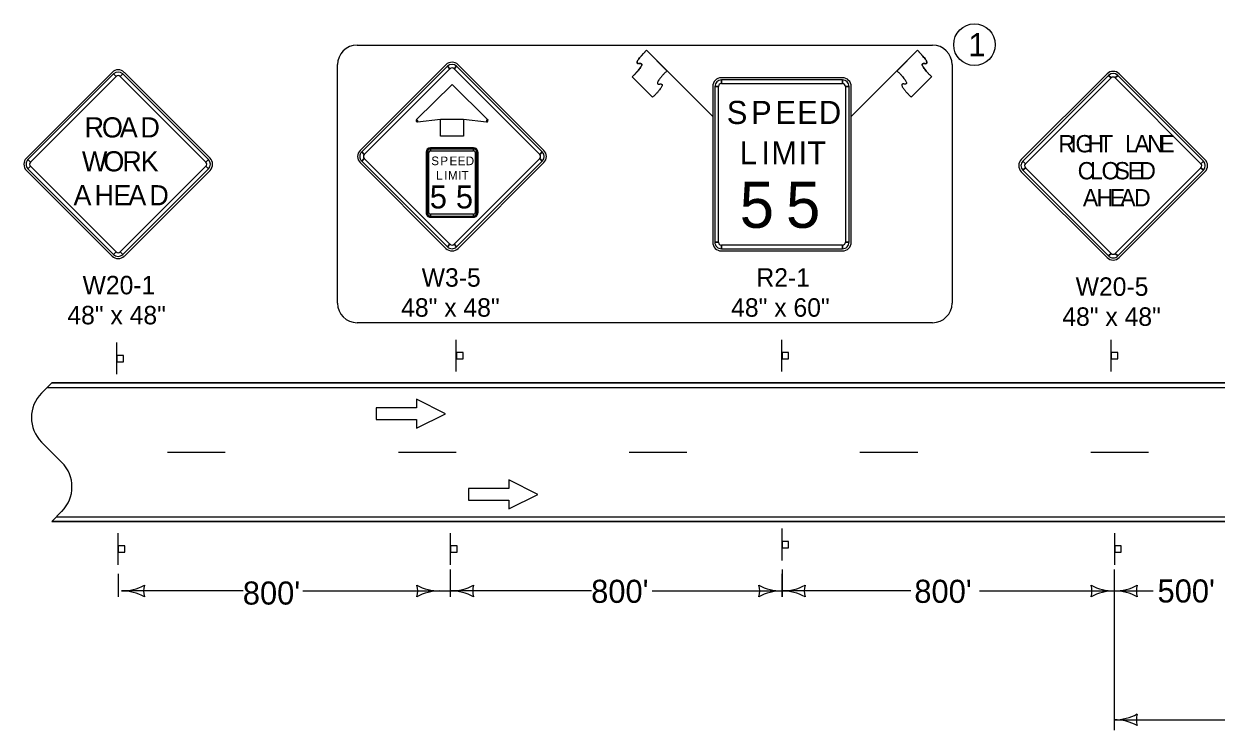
# Model space of a CAD drawing. Extents: x 10133 to 2270741, y 5363 to 1733450.
# Drawn here: x 28142 to 29175, y 11512 to 12124 of the extents above; entities that cross this region are included whole.
import ezdxf

# ---------------------------------------------------------------- set-up
doc = ezdxf.new("R2010")
doc.units = 0
for name, color, linetype in [('dsnNonPlotable', 7, 'Continuous'), ('dsnShtPlotShapeBatchPrint', 7, 'Continuous'), ('dsnStdBorder', 7, 'Continuous'), ('Level 12', 7, 'Continuous'), ('Level 2', 7, 'Continuous')]:
    doc.layers.add(name, color=color, linetype=linetype)

msp = doc.modelspace()

# ---------------------------------------------------------------- linework, layer by layer
at = {"layer": 'dsnNonPlotable'}
for p, q in [((28165.8, 11812.6), (28157, 11803.8)), ((28157, 11761.4), (28174.5, 11743.8)), ((28174.5, 11701.4), (28165.8, 11692.6)), ((28169.7, 11696.6), (29666.9, 11696.6))]:
    msp.add_line(p, q, dxfattribs=at)
for points in [[(28161.8, 11808.6), (30191.3, 11808.6)], [(28266.1, 11752.6), (28316.1, 11752.6)], [(28466.1, 11752.6), (28516.1, 11752.6)], [(28666.1, 11752.6), (28716.1, 11752.6)], [(28866, 11752.6), (28916, 11752.6)], [(29066, 11752.6), (29116, 11752.6)]]:
    msp.add_lwpolyline(points, dxfattribs=at)
for centre, start, end in [((28178.2, 11782.6), 135, 225), ((28153.3, 11722.6), 315, 45)]:
    msp.add_arc(centre, 30, start, end, dxfattribs=at)
at = {"layer": 'dsnShtPlotShapeBatchPrint'}
msp.add_circle((28965.2, 12105.7), 18, dxfattribs=at)
at = {"layer": 'dsnStdBorder'}
for p, q in [((28738.4, 12043.5), (28681.1, 12100.8)), ((28681.1, 12100.8), (28698.8, 12083.1)), ((28858.4, 12043.5), (28915.8, 12100.8)), ((28915.8, 12100.8), (28898.1, 12083.1)), ((28507.2, 12088.3), (28433, 12014.1)), ((28508.6, 12087), (28510.8, 12084.8)), ((28514.3, 12084.8), (28516.5, 12087)), ((28592.1, 12014.1), (28517.9, 12088.3)), ((28218, 12081.7), (28143.8, 12007.4)), ((28219.4, 12080.4), (28221.6, 12078.1)), ((28225.1, 12078.1), (28227.3, 12080.4)), ((28302.9, 12007.4), (28228.7, 12081.7)), ((28668.7, 12077.8), (28686.4, 12060.1)), ((28686.4, 12060.1), (28668.7, 12077.8)), ((28850.9, 12077), (28745.9, 12077)), ((28928.1, 12077.8), (28910.5, 12060.1)), ((28910.5, 12060.1), (28928.1, 12077.8)), ((29080.1, 12080.4), (29005.8, 12006.2)), ((29081.4, 12079.1), (29083.6, 12076.9)), ((29087.1, 12076.9), (29089.3, 12079.1)), ((29164.9, 12006.2), (29090.7, 12080.4)), ((28738.4, 12069.5), (28738.4, 11934.5)), ((28740.3, 12069.5), (28743.4, 12069.5)), ((28745.9, 12072), (28745.9, 12075.2)), ((28850.9, 12075.2), (28850.9, 12072)), ((28853.4, 12069.5), (28856.6, 12069.5)), ((28858.4, 11934.5), (28858.4, 12069.5)), ((28482.6, 12040), (28481.7, 12040.9)), ((28482.7, 12038.8), (28482.6, 12040)), ((28542.6, 12040), (28542.4, 12038.8)), ((28543.4, 12040.9), (28542.6, 12040)), ((28531.3, 12016.3), (28493.8, 12016.3)), ((28493.8, 12013.8), (28493.8, 12015.3)), ((28531.3, 12015.3), (28531.3, 12013.8)), ((28147.3, 12003.9), (28145.1, 12006.1)), ((28301.6, 12006.1), (28299.4, 12003.9)), ((28433, 12003.5), (28507.2, 11929.2)), ((28436.5, 12010.5), (28434.3, 12012.8)), ((28434.3, 12004.8), (28436.5, 12007)), ((28490.1, 12012.5), (28490.1, 11960)), ((28491, 12012.5), (28492.6, 12012.5)), ((28517.9, 11929.2), (28592.1, 12003.5)), ((28532.6, 12012.5), (28534.1, 12012.5)), ((28535.1, 11960), (28535.1, 12012.5)), ((28590.8, 12012.8), (28588.6, 12010.5)), ((28588.6, 12007), (28590.8, 12004.8)), ((29009.3, 12002.6), (29007.1, 12004.9)), ((29163.6, 12004.9), (29161.4, 12002.6)), ((28143.8, 11996.8), (28218, 11922.6)), ((28145.1, 11998.2), (28147.3, 12000.4)), ((28228.7, 11922.6), (28302.9, 11996.8)), ((28299.4, 12000.4), (28301.6, 11998.2)), ((29005.8, 11995.6), (29080.1, 11921.3)), ((29007.1, 11996.9), (29009.3, 11999.1)), ((29090.7, 11921.3), (29164.9, 11995.6)), ((29161.4, 11999.1), (29163.6, 11996.9)), ((28492.6, 11960), (28491, 11960)), ((28493.8, 11957.2), (28493.8, 11958.8)), ((28493.8, 11956.3), (28531.3, 11956.3)), ((28531.3, 11958.8), (28531.3, 11957.2)), ((28534.1, 11960), (28532.6, 11960)), ((28510.8, 11932.8), (28508.6, 11930.6)), ((28516.5, 11930.6), (28514.3, 11932.8)), ((28743.4, 11934.5), (28740.3, 11934.5)), ((28745.9, 11928.9), (28745.9, 11932)), ((28850.9, 11932), (28850.9, 11928.9)), ((28856.6, 11934.5), (28853.4, 11934.5)), ((28221.6, 11926.1), (28219.4, 11923.9)), ((28227.3, 11923.9), (28225.1, 11926.1)), ((28745.9, 11927), (28850.9, 11927)), ((29083.6, 11924.9), (29081.4, 11922.7)), ((29089.3, 11922.7), (29087.1, 11924.9)), ((28516.3, 11822.6), (28516.3, 11850.1)), ((28798.4, 11822.6), (28798.4, 11850.1)), ((29083.6, 11822.6), (29083.6, 11850.1)), ((28222.1, 11820.1), (28222.1, 11847.6)), ((28798.5, 11658.9), (28798.5, 11686.4)), ((28223.3, 11655.1), (28223.3, 11682.6)), ((28511.2, 11655.1), (28511.2, 11682.6)), ((29086.7, 11655.1), (29086.7, 11682.6))]:
    msp.add_line(p, q, dxfattribs=at)
for points in [[(28430.4, 12105.4), (28928.8, 12105.4)], [(28413.3, 11881.8), (28413.3, 12088.4)], [(28945.8, 12088.4), (28945.8, 11881.8)], [(28928.8, 11864.7), (28430.4, 11864.7)], [(28446.8, 11791), (28446.8, 11781), (28481.8, 11781), (28481.8, 11773.5), (28506.8, 11786), (28481.8, 11798.5), (28481.8, 11791), (28446.8, 11791)], [(28526.8, 11721.1), (28526.8, 11711.1), (28561.8, 11711.1), (28561.8, 11703.6), (28586.8, 11716.1), (28561.8, 11728.6), (28561.8, 11721.1), (28526.8, 11721.1)]]:
    msp.add_lwpolyline(points, dxfattribs=at)
for points in [[(28508.6, 12087), (28434.3, 12012.8), (28436.5, 12010.5), (28510.8, 12084.8), (28508.6, 12087)], [(28590.8, 12012.8), (28516.5, 12087), (28514.3, 12084.8), (28588.6, 12010.5), (28590.8, 12012.8)], [(28219.4, 12080.4), (28145.1, 12006.1), (28147.3, 12003.9), (28221.6, 12078.1), (28219.4, 12080.4)], [(28301.6, 12006.1), (28227.3, 12080.4), (28225.1, 12078.1), (28299.4, 12003.9), (28301.6, 12006.1)], [(29081.4, 12079.1), (29007.1, 12004.9), (29009.3, 12002.6), (29083.6, 12076.9), (29081.4, 12079.1)], [(29163.6, 12004.9), (29089.3, 12079.1), (29087.1, 12076.9), (29161.4, 12002.6), (29163.6, 12004.9)], [(28512.6, 12071.3), (28481.7, 12040.9), (28482.6, 12040), (28482.7, 12038.8), (28502.6, 12041.3), (28522.6, 12041.3), (28542.4, 12038.8), (28542.6, 12040), (28543.4, 12040.9), (28512.6, 12071.3)], [(28740.3, 12069.5), (28740.3, 11934.5), (28743.4, 11934.5), (28743.4, 12069.5), (28740.3, 12069.5)], [(28850.9, 12075.2), (28745.9, 12075.2), (28745.9, 12072), (28850.9, 12072), (28850.9, 12075.2)], [(28856.6, 11934.5), (28856.6, 12069.5), (28853.4, 12069.5), (28853.4, 11934.5), (28856.6, 11934.5)], [(28522.6, 12026.3), (28502.6, 12026.3), (28502.6, 12041.3), (28522.6, 12041.3), (28522.6, 12026.3)], [(28531.3, 12015.3), (28493.8, 12015.3), (28493.8, 12013.8), (28531.3, 12013.8), (28531.3, 12015.3)], [(28434.3, 12004.8), (28508.6, 11930.6), (28510.8, 11932.8), (28436.5, 12007), (28434.3, 12004.8)], [(28491, 12012.5), (28491, 11960), (28492.6, 11960), (28492.6, 12012.5), (28491, 12012.5)], [(28516.5, 11930.6), (28590.8, 12004.8), (28588.6, 12007), (28514.3, 11932.8), (28516.5, 11930.6)], [(28534.1, 11960), (28534.1, 12012.5), (28532.6, 12012.5), (28532.6, 11960), (28534.1, 11960)], [(28145.1, 11998.2), (28219.4, 11923.9), (28221.6, 11926.1), (28147.3, 12000.4), (28145.1, 11998.2)], [(28227.3, 11923.9), (28301.6, 11998.2), (28299.4, 12000.4), (28225.1, 11926.1), (28227.3, 11923.9)], [(29007.1, 11996.9), (29081.4, 11922.7), (29083.6, 11924.9), (29009.3, 11999.1), (29007.1, 11996.9)], [(29089.3, 11922.7), (29163.6, 11996.9), (29161.4, 11999.1), (29087.1, 11924.9), (29089.3, 11922.7)], [(28493.8, 11957.2), (28531.3, 11957.2), (28531.3, 11958.8), (28493.8, 11958.8), (28493.8, 11957.2)], [(28745.9, 11928.9), (28850.9, 11928.9), (28850.9, 11932), (28745.9, 11932), (28745.9, 11928.9)], [(28516.4, 11839.1), (28516.4, 11833.4), (28522.1, 11833.4), (28522.1, 11839.1)], [(28798.5, 11839.1), (28798.5, 11833.4), (28804.2, 11833.4), (28804.2, 11839.1)], [(29083.7, 11839.1), (29083.7, 11833.4), (29089.3, 11833.4), (29089.3, 11839.1)], [(28222.2, 11836.5), (28222.2, 11830.9), (28227.8, 11830.9), (28227.8, 11836.5)], [(28798.5, 11675.3), (28798.5, 11669.7), (28804.2, 11669.7), (28804.2, 11675.3)], [(28223.4, 11671.6), (28223.4, 11665.9), (28229, 11665.9), (28229, 11671.6)], [(28511.3, 11671.6), (28511.3, 11665.9), (28517, 11665.9), (28517, 11671.6)], [(29086.8, 11671.6), (29086.8, 11665.9), (29092.4, 11665.9), (29092.4, 11671.6)]]:
    msp.add_lwpolyline(points, close=True, dxfattribs=at)
for centre, radius, start, end in [((28430.4, 12088.4), 17, 90, 180), ((28928.8, 12088.4), 17, 0, 90), ((28512.6, 12083), 7.5, 45, 134.9997), ((28512.6, 12083), 5.62, 45, 134.9997), ((28223.3, 12076.4), 7.5, 45, 134.9997), ((28223.3, 12076.4), 5.62, 45, 134.9997), ((28223.3, 12076.4), 2.5, 45, 134.9997), ((28512.6, 12083), 2.5, 45, 134.9997), ((28745.9, 12069.5), 7.5, 90.0002, 179.9998), ((28850.9, 12069.5), 7.5, 0, 90.0002), ((29085.4, 12075.1), 7.5, 45, 134.9997), ((29085.4, 12075.1), 5.62, 45, 134.9997), ((29085.4, 12075.1), 2.5, 45, 134.9997), ((28745.9, 12069.5), 5.62, 90.0002, 179.9998), ((28745.9, 12069.5), 2.5, 90.0002, 179.9998), ((28850.9, 12069.5), 5.62, 0, 90.0002), ((28850.9, 12069.5), 2.5, 0, 90.0002), ((28482.6, 12040), 1.25, 134.9997, 277.1529), ((28542.6, 12040), 1.25, 262.8473, 44.9998), ((28438.3, 12008.8), 7.5, 134.9997, 225), ((28493.8, 12012.5), 3.75, 90.0002, 179.9998), ((28493.8, 12012.5), 2.81, 90.0002, 179.9998), ((28493.8, 12012.5), 1.25, 90.0002, 179.9998), ((28531.3, 12012.5), 3.75, 0, 90.0002), ((28531.3, 12012.5), 2.81, 0, 90.0002), ((28531.3, 12012.5), 1.25, 0, 90.0002), ((28586.8, 12008.8), 7.5, 315.0002, 44.9998), ((28149.1, 12002.1), 7.5, 134.9997, 225), ((28149.1, 12002.1), 5.62, 134.9997, 225), ((28149.1, 12002.1), 2.5, 134.9997, 225), ((28297.6, 12002.1), 2.5, 315.0002, 44.9998), ((28297.6, 12002.1), 5.62, 315.0002, 44.9998), ((28297.6, 12002.1), 7.5, 315.0002, 44.9998), ((28438.3, 12008.8), 5.62, 134.9997, 225), ((28438.3, 12008.8), 2.5, 134.9997, 225), ((28586.8, 12008.8), 2.5, 315.0002, 44.9998), ((28586.8, 12008.8), 5.62, 315.0002, 44.9998), ((29011.1, 12000.9), 7.5, 134.9997, 225), ((29011.1, 12000.9), 5.62, 134.9997, 225), ((29159.6, 12000.9), 5.62, 315.0002, 44.9998), ((29159.6, 12000.9), 7.5, 315.0002, 44.9998), ((29011.1, 12000.9), 2.5, 134.9997, 225), ((29159.6, 12000.9), 2.5, 315.0002, 44.9998), ((28493.8, 11960), 3.75, 179.9998, 270.0001), ((28493.8, 11960), 2.81, 179.9998, 270.0001), ((28493.8, 11960), 1.25, 179.9998, 270.0001), ((28531.3, 11960), 3.75, 270.0001, 0.0003), ((28531.3, 11960), 2.81, 270.0001, 0.0003), ((28531.3, 11960), 1.25, 270.0001, 0.0003), ((28512.6, 11934.5), 2.5, 225, 315.0002), ((28745.9, 11934.5), 7.5, 179.9998, 270.0001), ((28745.9, 11934.5), 5.62, 179.9998, 270.0001), ((28745.9, 11934.5), 2.5, 179.9998, 270.0001), ((28850.9, 11934.5), 7.5, 270.0001, 0.0003), ((28850.9, 11934.5), 5.62, 270.0001, 0.0003), ((28850.9, 11934.5), 2.5, 270.0001, 0.0003), ((28223.3, 11927.9), 7.5, 225, 315.0002), ((28223.3, 11927.9), 5.62, 225, 315.0002), ((28223.3, 11927.9), 2.5, 225, 315.0002), ((28512.6, 11934.5), 7.5, 225, 315.0002), ((28512.6, 11934.5), 5.62, 225, 315.0002), ((29085.4, 11926.6), 7.5, 225, 315.0002), ((29085.4, 11926.6), 5.62, 225, 315.0002), ((29085.4, 11926.6), 2.5, 225, 315.0002), ((28430.4, 11881.8), 17, 180, 270), ((28928.8, 11881.8), 17, 270, 0)]:
    msp.add_arc(centre, radius, start, end, dxfattribs=at)
for points in [[(28681.1, 12100.8), (28668.7, 12088.4), (28681.1, 12090.2), (28668.7, 12077.8)], [(28668.7, 12077.8), (28681.1, 12090.2), (28668.7, 12088.4), (28681.1, 12100.8)], [(28915.8, 12100.8), (28928.1, 12088.4), (28915.8, 12090.2), (28928.1, 12077.8)], [(28928.1, 12077.8), (28915.8, 12090.2), (28928.1, 12088.4), (28915.8, 12100.8)], [(28698.8, 12083.1), (28686.4, 12070.7), (28698.8, 12072.5), (28686.4, 12060.1)], [(28698.8, 12083.1), (28686.4, 12070.7), (28698.8, 12072.5), (28686.4, 12060.1)], [(28898.1, 12083.1), (28910.4, 12070.7), (28898.1, 12072.5), (28910.5, 12060.1)], [(28898.1, 12083.1), (28910.4, 12070.7), (28898.1, 12072.5), (28910.5, 12060.1)]]:
    msp.add_open_spline(points, degree=2, dxfattribs=at)
at = {"layer": 'Level 12'}
for p, q in [((28223.3, 11647.1), (28223.3, 11627.4)), ((28510.9, 11650.9), (28510.9, 11627.4)), ((28798.4, 11647.1), (28798.4, 11627.4)), ((28798.5, 11650.9), (28798.5, 11627.4)), ((29086.1, 11650.9), (29086.1, 11511.8)), ((28331.5, 11632.4), (28226.1, 11632.4)), ((28383.4, 11632.4), (28510.9, 11632.4)), ((28633.3, 11632.4), (28510.9, 11632.4)), ((28686, 11632.4), (28798.5, 11632.4)), ((28910.2, 11632.4), (28798.5, 11632.4)), ((28969.6, 11632.4), (29086.1, 11632.4)), ((29086.9, 11632.4), (29119.9, 11632.4)), ((29086.1, 11520.8), (29195.4, 11520.8))]:
    msp.add_line(p, q, dxfattribs=at)
for centre, radius, start, end in [((28226.1, 11674.9), 42.5, 270, 298.0725), ((28226.1, 11589.9), 42.5, 61.9275, 90), ((28261.7, 11632.4), 16.4, 162.2666, 197.7334), ((28466.5, 11632.4), 16.4, 342.2667, 17.7334), ((28502.1, 11674.9), 42.5, 241.9275, 270), ((28502.1, 11589.9), 42.5, 90, 118.0725), ((28511.2, 11674.9), 42.5, 270, 298.0725), ((28511.2, 11589.9), 42.5, 61.9275, 90), ((28546.9, 11632.4), 16.4, 162.2666, 197.7334), ((28762.8, 11632.4), 16.4, 342.2667, 17.7334), ((28798.4, 11674.9), 42.5, 241.9275, 270), ((28798.4, 11589.9), 42.5, 90, 118.0725), ((28798.4, 11674.9), 42.5, 270, 298.0725), ((28798.4, 11589.9), 42.5, 61.9275, 90), ((28834.1, 11632.4), 16.4, 162.2666, 197.7334), ((29050.6, 11632.4), 16.4, 342.2667, 17.7334), ((29086.3, 11674.9), 42.5, 241.9275, 270), ((29086.3, 11589.9), 42.5, 90, 118.0725), ((29086.3, 11674.9), 42.5, 270, 298.0725), ((29086.3, 11589.9), 42.5, 61.9275, 90), ((29121.9, 11632.4), 16.4, 162.2666, 197.7334), ((29086.3, 11563.3), 42.5, 270, 298.0725), ((29086.3, 11478.3), 42.5, 61.9275, 90), ((29121.9, 11520.8), 16.4, 162.2666, 197.7334)]:
    msp.add_arc(centre, radius, start, end, dxfattribs=at)
at = {"layer": 'Level 2'}
for p, q in [((28157, 11803.8), (28161.8, 11808.6)), ((28165.8, 11812.6), (28161.8, 11808.6)), ((28161.8, 11808.6), (29379, 11808.6)), ((28161.8, 11808.6), (29957.3, 11808.6)), ((28165.8, 11812.6), (30292.4, 11812.6)), ((29955.6, 11812.6), (28165.8, 11812.6)), ((28174.5, 11743.8), (28157, 11761.4)), ((28165.8, 11692.6), (28174.5, 11701.4)), ((28165.8, 11692.6), (30498, 11692.6)), ((29210.2, 11692.6), (28165.8, 11692.6))]:
    msp.add_line(p, q, dxfattribs=at)
msp.add_lwpolyline([(28161.8, 11808.6), (28161.8, 11808.6)], dxfattribs=at)
msp.add_lwpolyline([(28161.8, 11808.6), (28161.8, 11808.6)], dxfattribs=at)
for centre, start, end in [((28178.2, 11782.6), 135, 225), ((28153.3, 11722.6), 315, 45)]:
    msp.add_arc(centre, 30, start, end, dxfattribs=at)

# ---------------------------------------------------------------- texts
at = {"layer": 'dsnShtPlotShapeBatchPrint'}
msp.add_text('1', height=20, dxfattribs=at).set_placement((28960, 12095.7))
at = {"layer": 'dsnStdBorder'}
for s, height, p in [('S', 20, (28750.6, 12037)), ('P', 20, (28771.7, 12037)), ('E', 20, (28792.7, 12037)), ('E', 20, (28811.6, 12037)), ('D', 20, (28830.4, 12037)), ('R', 17.5, (28194.2, 12025.3)), ('O', 17.5, (28209.2, 12025.3)), ('A', 17.5, (28224.7, 12025.3)), ('D', 17.5, (28242.6, 12025.3)), ('R', 15, (29037.9, 12012.4)), ('I', 15, (29048.3, 12012.4)), ('G', 15, (29052.7, 12012.4)), ('H', 15, (29063.1, 12012.4)), ('T', 15, (29073.1, 12012.4)), ('L', 15, (29095.6, 12012.4)), ('A', 15, (29103.7, 12012.4)), ('N', 15, (29114.9, 12012.4)), ('E', 15, (29125.3, 12012.4)), ('L', 20, (28761.8, 12002)), ('I', 20, (28780.6, 12002)), ('M', 20, (28789.2, 12002)), ('I', 20, (28812.8, 12002)), ('T', 20, (28820.4, 12002)), ('W', 17.5, (28191.9, 11995.9)), ('O', 17.5, (28210.5, 11995.9)), ('R', 17.5, (28226.9, 11995.9)), ('K', 17.5, (28242.8, 11995.9)), ('S', 7.5, (28494.6, 12001.3)), ('P', 7.5, (28502.5, 12001.3)), ('E', 7.5, (28510.4, 12001.3)), ('E', 7.5, (28517.5, 12001.3)), ('D', 7.5, (28524.5, 12001.3)), ('C', 15, (29054.6, 11989)), ('L', 15, (29065.3, 11989)), ('O', 15, (29075.3, 11989)), ('S', 15, (29086.5, 11989)), ('E', 15, (29097.9, 11989)), ('D', 15, (29107.9, 11989)), ('L', 7.5, (28498.8, 11988.8)), ('I', 7.5, (28505.9, 11988.8)), ('M', 7.5, (28509.1, 11988.8)), ('I', 7.5, (28517.9, 11988.8)), ('T', 7.5, (28520.8, 11988.8)), ('A', 17.5, (28184.6, 11966.5)), ('H', 17.5, (28202.8, 11966.5)), ('E', 17.5, (28219.1, 11966.5)), ('A', 17.5, (28232.1, 11966.5)), ('D', 17.5, (28250.3, 11966.5)), ('5', 20, (28493.3, 11963.8)), ('5', 20, (28515.9, 11963.8)), ('5', 40, (28761.8, 11947)), ('5', 40, (28801.9, 11947)), ('A', 15, (29059.1, 11965.6)), ('H', 15, (29071, 11965.6)), ('E', 15, (29082.3, 11965.6)), ('A', 15, (29091.5, 11965.6)), ('D', 15, (29103.4, 11965.6)), ('W3-5', 16, (28486.3, 11896)), ('R2-1', 16, (28776.3, 11896)), ('W20-1', 16, (28192.5, 11889.4)), ('W20-5', 16, (29052.9, 11888.1)), ('48" x 48"', 16, (28179.3, 11863.4)), ('48" x 48"', 16, (28468.5, 11870)), ('48" x 60"', 16, (28754.4, 11870)), ('48" x 48"', 16, (29041.3, 11862.1))]:
    msp.add_text(s, height=height, dxfattribs=at).set_placement(p)
at = {"layer": 'Level 12'}
for s, p in [("800'", (28633.1, 11622.1)), ("800'", (28913.1, 11622.1)), ("500'", (29123.8, 11622.4)), ("800'", (28331.3, 11620.6))]:
    msp.add_text(s, height=20, dxfattribs=at).set_placement(p)

doc.saveas('drawing.dxf')
